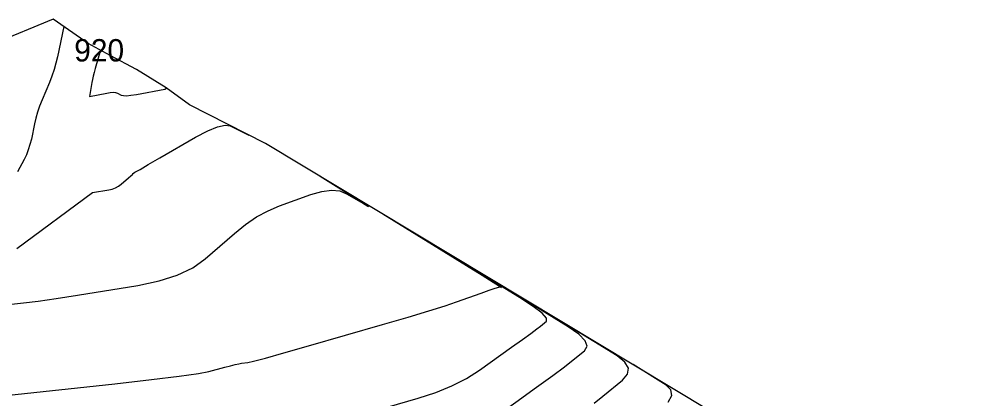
# Model space of a CAD drawing. Extents: x 2175772 to 2185556, y 721391 to 722853.
# Drawn here: x 2178888.4 to 2179007.5, y 722173.5 to 722221.1 of the extents above; entities that cross this region are included whole.
import ezdxf

# ---------------------------------------------------------------- set-up
doc = ezdxf.new("R2010")
doc.units = 0
for name, color, linetype in [('DT_X_Contour_Major', 7, 'Continuous'), ('DT_X_Contour_Minor', 7, 'Continuous'), ('DT_X_TIN_Hull', 7, 'Continuous')]:
    doc.layers.add(name, color=color, linetype=linetype)

msp = doc.modelspace()

# ---------------------------------------------------------------- linework, layer by layer
at = {"layer": 'DT_X_Contour_Major'}
for points in [[(2178898.57, 722217.23), (2178897.9, 722214.94), (2178897.77, 722214.46), (2178897.65, 722214.01), (2178897.56, 722213.59), (2178897.48, 722213.2), (2178897.18, 722211.45), (2178899.36, 722211.88), (2178899.79, 722211.95), (2178900.15, 722211.97), (2178900.44, 722211.95), (2178900.67, 722211.87), (2178901.17, 722211.62), (2178901.43, 722211.55), (2178901.83, 722211.54), (2178902.38, 722211.59), (2178903.07, 722211.7), (2178906.63, 722212.35), (2178906.82, 722212.48)], [(2178941.68, 722166.78), (2178942.86, 722167.62), (2178950.57, 722173.15), (2178953.17, 722175.02), (2178955.21, 722176.5), (2178956.67, 722177.59), (2178957.56, 722178.28), (2178959.18, 722179.6), (2178959.51, 722180.16), (2178959.28, 722180.85), (2178958.49, 722181.66), (2178957.15, 722182.6), (2178949.59, 722187.28)]]:
    msp.add_lwpolyline(points, dxfattribs=at)
at = {"layer": 'DT_X_Contour_Minor'}
for points in [[(2178893.95, 722220.23), (2178893.17, 722216.43), (2178892.98, 722215.62), (2178892.75, 722214.81), (2178892.47, 722214), (2178892.16, 722213.19), (2178891.26, 722211.04), (2178890.94, 722210.25), (2178890.67, 722209.47), (2178890.46, 722208.73), (2178890.29, 722208), (2178889.9, 722206.1), (2178889.73, 722205.41), (2178889.52, 722204.75), (2178889.28, 722204.12), (2178888.99, 722203.54), (2178888.17, 722202.02)], [(2178888.08, 722192.39), (2178897.55, 722199.41), (2178899.61, 722199.74), (2178900.03, 722199.84), (2178900.43, 722199.99), (2178900.81, 722200.2), (2178901.16, 722200.46), (2178902.05, 722201.24), (2178902.34, 722201.5), (2178902.55, 722201.68), (2178902.67, 722201.79), (2178902.7, 722201.83), (2178902.68, 722201.83), (2178902.88, 722201.95), (2178903.51, 722202.31), (2178904.55, 722202.92), (2178906.01, 722203.76), (2178910.46, 722206.34), (2178911.99, 722207.15), (2178913.22, 722207.66), (2178914.16, 722207.87), (2178914.81, 722207.77), (2178917.16, 722206.6)], [(2178887.42, 722185.44), (2178888.9, 722185.59), (2178890.76, 722185.82), (2178893.01, 722186.15), (2178895.66, 722186.56), (2178903.24, 722187.78), (2178905.89, 722188.33), (2178908.18, 722189.07), (2178910.11, 722189.99), (2178911.66, 722191.1), (2178915.33, 722194.29), (2178916.71, 722195.41), (2178918.12, 722196.35), (2178919.54, 722197.13), (2178921, 722197.74), (2178924.9, 722199.15), (2178926.27, 722199.55), (2178927.48, 722199.71), (2178928.52, 722199.62), (2178929.39, 722199.27), (2178931.49, 722198.03), (2178932.05, 722197.7), (2178932.14, 722197.65), (2178931.78, 722197.88), (2178930.96, 722198.39), (2178926.07, 722201.42)], [(2178886.7, 722173.97), (2178900.37, 722175.46), (2178904.94, 722175.98), (2178908.43, 722176.4), (2178910.82, 722176.74), (2178912.12, 722176.99), (2178914.14, 722177.53), (2178914.83, 722177.71), (2178915.42, 722177.86), (2178915.89, 722177.96), (2178916.24, 722178.02), (2178917.03, 722178.12), (2178917.73, 722178.28), (2178919.22, 722178.68), (2178921.51, 722179.32), (2178924.6, 722180.2), (2178933.89, 722182.87), (2178937.08, 722183.8), (2178939.69, 722184.58), (2178941.71, 722185.21), (2178943.16, 722185.7), (2178946.23, 722186.81), (2178947.25, 722187.17), (2178947.99, 722187.42), (2178948.45, 722187.56), (2178948.64, 722187.58), (2178948.78, 722187.5), (2178948.55, 722187.65), (2178947.74, 722188.15), (2178946.35, 722189), (2178944.39, 722190.22), (2178933.91, 722196.7)], [(2178932.15, 722171.86), (2178938.34, 722173.64), (2178940.56, 722174.36), (2178942.58, 722175.18), (2178944.4, 722176.11), (2178946.01, 722177.14), (2178950.04, 722180.03), (2178951.4, 722181.01), (2178952.45, 722181.77), (2178953.2, 722182.33), (2178953.65, 722182.67), (2178954.43, 722183.31), (2178954.43, 722183.67), (2178953.87, 722184.28), (2178952.74, 722185.14), (2178951.03, 722186.25), (2178941.75, 722191.99)], [(2178960.39, 722173.03), (2178961.48, 722173.89), (2178963.93, 722175.9), (2178964.58, 722176.65), (2178964.69, 722177.41), (2178964.25, 722178.18), (2178963.27, 722178.95), (2178957.43, 722182.56)], [(2178969.66, 722173.14), (2178970.1, 722173.98), (2178970.01, 722174.69), (2178969.39, 722175.3), (2178965.27, 722177.85)]]:
    msp.add_lwpolyline(points, dxfattribs=at)
at = {"layer": 'DT_X_TIN_Hull'}
msp.add_lwpolyline([(2179107.62, 722089.39), (2179075.12, 722109.69), (2179069.22, 722113.13), (2179059.79, 722118.52), (2179054.81, 722121.98), (2179049.44, 722125.39), (2179049.52, 722126.42), (2178984.03, 722166.57), (2178919.21, 722205.54), (2178909.71, 722210.4), (2178906.79, 722212.51), (2178903.07, 722214.83), (2178899.76, 722216.57), (2178897.01, 722218.1), (2178892.62, 722221.15), (2178877.64, 722214.96), (2178841.51, 722186.7), (2178759.74, 722159.66), (2178721.08, 722141.18), (2178706.95, 722109.71), (2178684.5, 722059.42)], dxfattribs=at)

# ---------------------------------------------------------------- texts
at = {"layer": 'DT_X_Contour_Major'}
msp.add_text('920', height=2.8, dxfattribs=at).set_placement((2178895.27, 722215.83))

doc.saveas('drawing.dxf')
